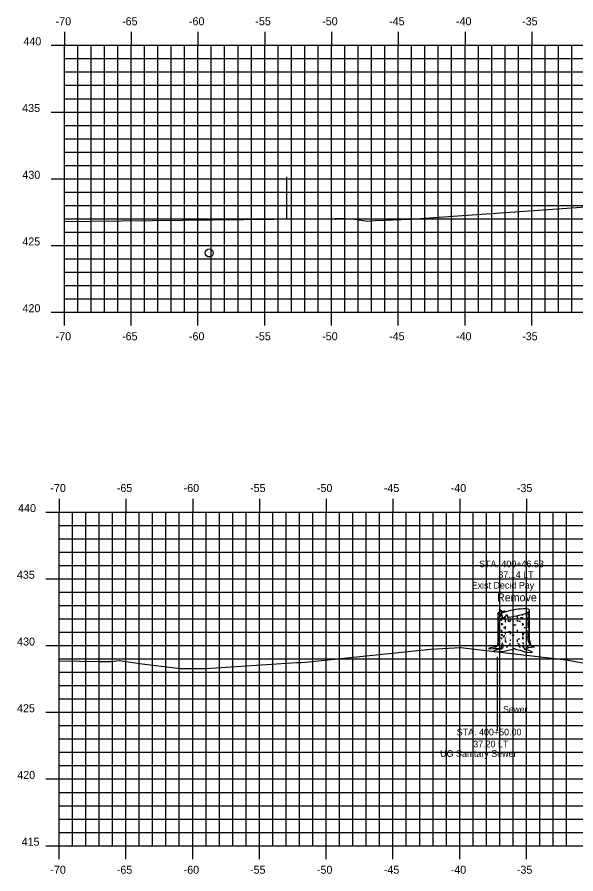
# Model space of a CAD drawing. Extents: x -161 to 764, y 111 to 210.
# Drawn here: x 81 to 122.9, y 125.1 to 189.3 of the extents above; entities that cross this region are included whole.
import ezdxf

# ---------------------------------------------------------------- set-up
doc = ezdxf.new("R2010")
doc.units = 0
for name, color, linetype in [('D_Text_Monospaced', 7, 'Continuous'), ('D_Text_Standard', 7, 'Continuous'), ('H_V ANNOTATION', 7, 'Continuous'), ('MAJOR', 7, 'Continuous'), ('MINOR', 7, 'Continuous'), ('S_Drainage_Culvert_Top', 7, 'Continuous'), ('S_Drainage_Invert', 7, 'Continuous'), ('S_Roadway_Centerline', 7, 'Continuous'), ('S_Trees_Decid_Pay', 7, 'Continuous'), ('S_Utilities_UG_Sanitary_Sewer', 7, 'Continuous')]:
    doc.layers.add(name, color=color, linetype=linetype)

msp = doc.modelspace()

# ---------------------------------------------------------------- linework, layer by layer
at = {"layer": 'MAJOR'}
for p, q in [((84.563, 188.143), (84.563, 187.141)), ((89.563, 188.143), (89.563, 187.141)), ((94.563, 188.143), (94.563, 187.141)), ((99.563, 188.143), (99.563, 187.141)), ((104.563, 188.143), (104.563, 187.141)), ((109.563, 188.143), (109.563, 187.141)), ((114.563, 188.143), (114.563, 187.141)), ((119.563, 188.143), (119.563, 187.141)), ((83.561, 187.141), (84.563, 187.141)), ((84.563, 187.141), (224.563, 187.141)), ((84.563, 167.141), (84.563, 187.141)), ((84.563, 167.141), (84.563, 187.141)), ((84.563, 187.141), (224.563, 187.141)), ((89.563, 167.141), (89.563, 187.141)), ((94.563, 167.141), (94.563, 187.141)), ((99.563, 167.141), (99.563, 187.141)), ((104.563, 167.141), (104.563, 187.141)), ((109.563, 167.141), (109.563, 187.141)), ((114.563, 167.141), (114.563, 187.141)), ((119.563, 167.141), (119.563, 187.141)), ((83.561, 182.141), (84.563, 182.141)), ((84.563, 182.141), (224.563, 182.141)), ((83.561, 177.141), (84.563, 177.141)), ((84.563, 177.141), (224.563, 177.141)), ((83.561, 172.141), (84.563, 172.141)), ((84.563, 172.141), (224.563, 172.141)), ((83.561, 167.141), (84.563, 167.141)), ((84.563, 167.141), (224.563, 167.141)), ((84.563, 167.141), (224.563, 167.141)), ((84.563, 166.139), (84.563, 167.141)), ((89.563, 166.139), (89.563, 167.141)), ((94.563, 166.139), (94.563, 167.141)), ((99.563, 166.139), (99.563, 167.141)), ((104.563, 166.139), (104.563, 167.141)), ((109.563, 166.139), (109.563, 167.141)), ((114.563, 166.139), (114.563, 167.141)), ((119.563, 166.139), (119.563, 167.141)), ((84.168, 153.171), (84.168, 152.169)), ((89.168, 153.171), (89.168, 152.169)), ((94.168, 153.171), (94.168, 152.169)), ((99.168, 153.171), (99.168, 152.169)), ((104.168, 153.171), (104.168, 152.169)), ((109.168, 153.171), (109.168, 152.169)), ((114.168, 153.171), (114.168, 152.169)), ((119.168, 153.171), (119.168, 152.169)), ((83.166, 152.169), (84.168, 152.169)), ((84.168, 152.169), (224.168, 152.169)), ((84.168, 127.169), (84.168, 152.169)), ((84.168, 127.169), (84.168, 152.169)), ((84.168, 152.169), (224.168, 152.169)), ((89.168, 127.169), (89.168, 152.169)), ((94.168, 127.169), (94.168, 152.169)), ((99.168, 127.169), (99.168, 152.169)), ((104.168, 127.169), (104.168, 152.169)), ((109.168, 127.169), (109.168, 152.169)), ((114.168, 127.169), (114.168, 152.169)), ((119.168, 127.169), (119.168, 152.169)), ((83.166, 147.169), (84.168, 147.169)), ((84.168, 147.169), (224.168, 147.169)), ((83.166, 142.169), (84.168, 142.169)), ((84.168, 142.169), (224.168, 142.169)), ((83.166, 137.169), (84.168, 137.169)), ((84.168, 137.169), (224.168, 137.169)), ((83.166, 132.169), (84.168, 132.169)), ((84.168, 132.169), (224.168, 132.169)), ((83.166, 127.169), (84.168, 127.169)), ((84.168, 127.169), (224.168, 127.169)), ((84.168, 127.169), (224.168, 127.169)), ((84.168, 126.167), (84.168, 127.169)), ((89.168, 126.167), (89.168, 127.169)), ((94.168, 126.167), (94.168, 127.169)), ((99.168, 126.167), (99.168, 127.169)), ((104.168, 126.167), (104.168, 127.169)), ((109.168, 126.167), (109.168, 127.169)), ((114.168, 126.167), (114.168, 127.169)), ((119.168, 126.167), (119.168, 127.169))]:
    msp.add_line(p, q, dxfattribs=at)
at = {"layer": 'MINOR'}
for p, q in [((85.563, 167.141), (85.563, 187.141)), ((86.563, 167.141), (86.563, 187.141)), ((87.563, 167.141), (87.563, 187.141)), ((88.563, 167.141), (88.563, 187.141)), ((90.563, 167.141), (90.563, 187.141)), ((91.563, 167.141), (91.563, 187.141)), ((92.563, 167.141), (92.563, 187.141)), ((93.563, 167.141), (93.563, 187.141)), ((95.563, 167.141), (95.563, 187.141)), ((96.563, 167.141), (96.563, 187.141)), ((97.563, 167.141), (97.563, 187.141)), ((98.563, 167.141), (98.563, 187.141)), ((100.563, 167.141), (100.563, 187.141)), ((101.563, 167.141), (101.563, 187.141)), ((102.563, 167.141), (102.563, 187.141)), ((103.563, 167.141), (103.563, 187.141)), ((105.563, 167.141), (105.563, 187.141)), ((106.563, 167.141), (106.563, 187.141)), ((107.563, 167.141), (107.563, 187.141)), ((108.563, 167.141), (108.563, 187.141)), ((110.563, 167.141), (110.563, 187.141)), ((111.563, 167.141), (111.563, 187.141)), ((112.563, 167.141), (112.563, 187.141)), ((113.563, 167.141), (113.563, 187.141)), ((115.563, 167.141), (115.563, 187.141)), ((116.563, 167.141), (116.563, 187.141)), ((117.563, 167.141), (117.563, 187.141)), ((118.563, 167.141), (118.563, 187.141)), ((120.563, 167.141), (120.563, 187.141)), ((121.563, 167.141), (121.563, 187.141)), ((122.563, 167.141), (122.563, 187.141)), ((84.563, 186.141), (224.563, 186.141)), ((84.563, 186.141), (85.565, 186.141)), ((84.563, 185.141), (224.563, 185.141)), ((84.563, 185.141), (85.565, 185.141)), ((84.563, 184.141), (224.563, 184.141)), ((84.563, 184.141), (85.565, 184.141)), ((84.563, 183.141), (224.563, 183.141)), ((84.563, 183.141), (85.565, 183.141)), ((84.563, 181.141), (224.563, 181.141)), ((84.563, 181.141), (85.565, 181.141)), ((84.563, 180.141), (224.563, 180.141)), ((84.563, 180.141), (85.565, 180.141)), ((84.563, 179.141), (224.563, 179.141)), ((84.563, 179.141), (85.565, 179.141)), ((84.563, 178.141), (224.563, 178.141)), ((84.563, 178.141), (85.565, 178.141)), ((84.563, 176.141), (224.563, 176.141)), ((84.563, 176.141), (85.565, 176.141)), ((84.563, 175.141), (224.563, 175.141)), ((84.563, 175.141), (85.565, 175.141)), ((84.563, 174.141), (224.563, 174.141)), ((84.563, 174.141), (85.565, 174.141)), ((84.563, 173.141), (224.563, 173.141)), ((84.563, 173.141), (85.565, 173.141)), ((84.563, 171.141), (224.563, 171.141)), ((84.563, 171.141), (85.565, 171.141)), ((84.563, 170.141), (224.563, 170.141)), ((84.563, 170.141), (85.565, 170.141)), ((84.563, 169.141), (224.563, 169.141)), ((84.563, 169.141), (85.565, 169.141)), ((84.563, 168.141), (224.563, 168.141)), ((84.563, 168.141), (85.565, 168.141)), ((85.168, 127.169), (85.168, 152.169)), ((86.168, 127.169), (86.168, 152.169)), ((87.168, 127.169), (87.168, 152.169)), ((88.168, 127.169), (88.168, 152.169)), ((90.168, 127.169), (90.168, 152.169)), ((91.168, 127.169), (91.168, 152.169)), ((92.168, 127.169), (92.168, 152.169)), ((93.168, 127.169), (93.168, 152.169)), ((95.168, 127.169), (95.168, 152.169)), ((96.168, 127.169), (96.168, 152.169)), ((97.168, 127.169), (97.168, 152.169)), ((98.168, 127.169), (98.168, 152.169)), ((100.168, 127.169), (100.168, 152.169)), ((101.168, 127.169), (101.168, 152.169)), ((102.168, 127.169), (102.168, 152.169)), ((103.168, 127.169), (103.168, 152.169)), ((105.168, 127.169), (105.168, 152.169)), ((106.168, 127.169), (106.168, 152.169)), ((107.168, 127.169), (107.168, 152.169)), ((108.168, 127.169), (108.168, 152.169)), ((110.168, 127.169), (110.168, 152.169)), ((111.168, 127.169), (111.168, 152.169)), ((112.168, 127.169), (112.168, 152.169)), ((113.168, 127.169), (113.168, 152.169)), ((115.168, 127.169), (115.168, 152.169)), ((116.168, 127.169), (116.168, 152.169)), ((117.168, 127.169), (117.168, 152.169)), ((118.168, 127.169), (118.168, 152.169)), ((120.168, 127.169), (120.168, 152.169)), ((121.168, 127.169), (121.168, 152.169)), ((122.168, 127.169), (122.168, 152.169)), ((84.168, 151.169), (224.168, 151.169)), ((84.168, 151.169), (85.17, 151.169)), ((84.168, 150.169), (224.168, 150.169)), ((84.168, 150.169), (85.17, 150.169)), ((84.168, 149.169), (224.168, 149.169)), ((84.168, 149.169), (85.17, 149.169)), ((84.168, 148.169), (224.168, 148.169)), ((84.168, 148.169), (85.17, 148.169)), ((84.168, 146.169), (224.168, 146.169)), ((84.168, 146.169), (85.17, 146.169)), ((84.168, 145.169), (224.168, 145.169)), ((84.168, 145.169), (85.17, 145.169)), ((84.168, 144.169), (224.168, 144.169)), ((84.168, 144.169), (85.17, 144.169)), ((84.168, 143.169), (224.168, 143.169)), ((84.168, 143.169), (85.17, 143.169)), ((84.168, 141.169), (224.168, 141.169)), ((84.168, 141.169), (85.17, 141.169)), ((84.168, 140.169), (224.168, 140.169)), ((84.168, 140.169), (85.17, 140.169)), ((84.168, 139.169), (224.168, 139.169)), ((84.168, 139.169), (85.17, 139.169)), ((84.168, 138.169), (224.168, 138.169)), ((84.168, 138.169), (85.17, 138.169)), ((84.168, 136.169), (224.168, 136.169)), ((84.168, 136.169), (85.17, 136.169)), ((84.168, 135.169), (224.168, 135.169)), ((84.168, 135.169), (85.17, 135.169)), ((84.168, 134.169), (224.168, 134.169)), ((84.168, 134.169), (85.17, 134.169)), ((84.168, 133.169), (224.168, 133.169)), ((84.168, 133.169), (85.17, 133.169)), ((84.168, 131.169), (224.168, 131.169)), ((84.168, 131.169), (85.17, 131.169)), ((84.168, 130.169), (224.168, 130.169)), ((84.168, 130.169), (85.17, 130.169)), ((84.168, 129.169), (224.168, 129.169)), ((84.168, 129.169), (85.17, 129.169)), ((84.168, 128.169), (224.168, 128.169)), ((84.168, 128.169), (85.17, 128.169))]:
    msp.add_line(p, q, dxfattribs=at)
at = {"layer": 'S_Drainage_Culvert_Top'}
msp.add_line((101.194, 177.288), (101.194, 174.133), dxfattribs=at)
at = {"layer": 'S_Drainage_Invert'}
msp.add_circle((95.412, 171.579), 0.3, dxfattribs=at)
at = {"layer": 'S_Roadway_Centerline'}
for points in [[(84.563, 173.937), (86.565, 173.962), (104.807, 174.158), (105.264, 174.178), (106.296, 174.117), (107.265, 173.972), (107.828, 174.003), (110.477, 174.125), (125.033, 175.141), (130.13, 175.365), (150.707, 176.49), (164.616, 177.272), (172.022, 177.096), (179.352, 177.108), (186.535, 177.007), (193.367, 177.096), (200.259, 176.65), (200.943, 176.413), (208.506, 176.123), (214.429, 175.907), (217.362, 175.08), (224.563, 174.564)], [(84.168, 141.029), (87.203, 140.965), (88.029, 140.976), (88.313, 140.998), (88.651, 141.037), (90.373, 140.805), (93.242, 140.453), (95.167, 140.458), (101.949, 140.906), (102.274, 140.898), (102.611, 140.922), (111.988, 141.903), (114.233, 142.01), (122.137, 141.107), (126.555, 140.289), (130.319, 140.459), (134.216, 140.564), (135.604, 140.561), (137.09, 140.487), (138.288, 140.324), (142.564, 140.487), (147.286, 140.317), (152.685, 140.854), (168.169, 142.293)]]:
    msp.add_lwpolyline(points, dxfattribs=at)
at = {"layer": 'S_Trees_Decid_Pay'}
for p, q in [((117.223, 144.514), (117.223, 144.34)), ((118.863, 144.506), (118.863, 144.42)), ((119.268, 144.673), (119.268, 144.42)), ((119.348, 144.718), (119.348, 144.597)), ((119.348, 144.545), (119.348, 144.331)), ((117.073, 144.314), (117.073, 144.06)), ((117.073, 143.962), (117.073, 143.493)), ((117.159, 144.168), (117.159, 143.957)), ((117.159, 143.891), (117.159, 143.743)), ((117.308, 144.266), (117.308, 144.061)), ((117.308, 143.854), (117.308, 143.699)), ((117.569, 144.268), (117.569, 144.148)), ((117.569, 144.096), (117.569, 143.911)), ((117.807, 143.996), (117.812, 144.103)), ((117.934, 144.168), (117.934, 143.989)), ((118.48, 144.405), (118.48, 144.125)), ((118.48, 144.06), (118.48, 143.957)), ((118.863, 144.279), (118.863, 144.14)), ((118.863, 143.854), (118.863, 143.662)), ((119.135, 144.42), (119.135, 144.228)), ((119.135, 143.977), (119.135, 143.699)), ((119.268, 144.323), (119.268, 144.06)), ((119.268, 143.962), (119.268, 143.654)), ((119.348, 144.286), (119.348, 143.948)), ((119.348, 143.831), (119.348, 143.47)), ((117.073, 143.442), (117.073, 143.308)), ((117.073, 143.25), (117.073, 142.925)), ((117.159, 143.565), (117.159, 143.265)), ((117.159, 143.228), (117.159, 142.985)), ((117.308, 143.336), (117.308, 143.117)), ((117.569, 143.625), (117.569, 143.397)), ((117.569, 143.199), (117.569, 143.014)), ((117.934, 143.21), (117.934, 143.014)), ((118.48, 143.345), (118.48, 143.125)), ((118.863, 143.182), (118.863, 142.974)), ((119.135, 143.654), (119.135, 143.545)), ((119.135, 143.411), (119.135, 143.182)), ((119.268, 143.565), (119.268, 143.499)), ((119.268, 143.265), (119.268, 143.168)), ((119.348, 143.434), (119.348, 142.985)), ((117.073, 142.896), (117.073, 142.476)), ((117.159, 142.874), (117.159, 142.733)), ((117.159, 142.602), (117.159, 142.445)), ((117.308, 143.017), (117.308, 142.896)), ((117.308, 142.745), (117.308, 142.647)), ((117.569, 142.779), (117.569, 142.702)), ((117.569, 142.625), (117.569, 142.451)), ((117.934, 142.63), (117.934, 142.527)), ((118.48, 142.625), (118.48, 142.451)), ((118.863, 142.853), (118.863, 142.653)), ((119.135, 142.853), (119.135, 142.47)), ((119.268, 143.117), (119.268, 142.756)), ((119.268, 142.705), (119.268, 142.538)), ((119.348, 142.919), (119.348, 142.637)), ((117.077, 142.373), (117.062, 142.256)), ((118.858, 142.396), (118.938, 142.264))]:
    msp.add_line(p, q, dxfattribs=at)
for points in [[(117.023, 144.588), (117.023, 142.451), (117.003, 142.31), (116.997, 142.184), (116.953, 142.097), (116.861, 142.048), (116.725, 142.048), (116.482, 141.992), (116.315, 141.943), (116.457, 141.912), (116.694, 141.949), (116.904, 141.937), (117.165, 141.943), (117.289, 141.961), (117.32, 141.918), (117.382, 141.961), (117.283, 141.894), (117.048, 141.869), (116.818, 141.807), (116.688, 141.737), (116.787, 141.693), (117.209, 141.712), (117.487, 141.756), (117.785, 141.832), (118.071, 141.869), (118.176, 141.869), (118.195, 141.949), (118.263, 141.955), (118.43, 141.869), (118.716, 141.813), (119.014, 141.706), (119.474, 141.657), (119.628, 141.669), (119.286, 141.819), (119.083, 141.85), (119.094, 141.924), (119.354, 142.023), (119.53, 142.054), (119.77, 142.066), (119.572, 142.104), (119.51, 142.14), (119.486, 142.227), (119.474, 142.396), (119.428, 142.482), (119.4, 142.723), (119.4, 144.809)], [(117.379, 144.261), (117.371, 144.405), (117.326, 144.397), (117.312, 144.772), (117.217, 144.78), (117.203, 144.86), (117.165, 144.523), (117.12, 144.617), (117.1, 144.463), (117.023, 144.588), (117.029, 144.399)], [(117.023, 144.588), (117.069, 144.611), (117.091, 144.677), (117.143, 144.7), (117.176, 144.625)], [(117.402, 144.627), (117.423, 144.735), (117.554, 144.766), (117.562, 144.678)], [(117.541, 144.266), (117.577, 144.369), (117.643, 144.375), (117.643, 144.457), (117.717, 144.463), (117.742, 144.283)], [(117.431, 142.896), (117.423, 142.822), (117.497, 142.816), (117.511, 142.933)], [(118.976, 142.988), (118.975, 143.065), (118.967, 143.131)], [(119.35, 142.565), (119.41, 142.404), (119.424, 142.279), (119.416, 142.182)], [(117.143, 142.381), (117.136, 142.256), (117.054, 142.161)], [(117.289, 141.961), (117.308, 142.14), (117.369, 142.277), (117.363, 142.377)], [(117.48, 142.209), (117.406, 142.14), (117.388, 142.042), (117.382, 141.961)], [(117.932, 142.344), (117.915, 142.19), (117.717, 142.109), (117.672, 142.006)], [(118.497, 142.336), (118.6, 142.285), (118.615, 142.079), (118.718, 142.05)], [(119.083, 141.85), (118.996, 141.992), (118.864, 142.134)], [(119.152, 142.41), (119.152, 142.205), (119.21, 142.095), (119.307, 142.079)], [(119.293, 142.484), (119.364, 142.381), (119.364, 142.256)]]:
    msp.add_lwpolyline(points, dxfattribs=at)
for centre, radius, start, end in [((117.833, 143.401), 1.299, 107.86134, 113.3069), ((119.313, 138.807), 6.126, 100.77788, 107.86134), ((119.313, 138.807), 6.126, 93.69441, 100.77788), ((117.111, 150.376), 6.126, 280.77788, 287.86134), ((119.002, 143.624), 1.299, 78.27788, 93.69441), ((118.591, 145.782), 1.299, 287.86134, 303.27788), ((119.168, 144.427), 0.48, 69.98432, 78.27788), ((119.041, 145.097), 0.48, 303.27788, 311.57144), ((119.276, 144.723), 0.164, 55.77788, 69.98432), ((119.261, 144.552), 0.166, 301.67004, 315), ((119.25, 144.861), 0.164, 311.57144, 325.77788), ((119.308, 144.77), 0.107, 45.9547, 55.77788), ((119.301, 144.511), 0.109, 315, 324.82628), ((119.338, 144.801), 0.0645, 33.27788, 45.9547), ((119.297, 144.829), 0.107, 325.77788, 335.60106), ((119.337, 144.486), 0.0657, 324.82628, 337.5), ((119.347, 144.806), 0.0544, 22.46002, 33.27788), ((119.336, 144.811), 0.0645, 335.60106, 348.27788), ((119.354, 144.809), 0.0467, 10.77788, 22.46002), ((119.346, 144.482), 0.0554, 337.5, 348.31854), ((119.346, 144.809), 0.0544, 348.27788, 359.09574), ((119.354, 144.809), 0.0467, 359.09574, 10.77788), ((117.071, 144.22), 0.0476, 180, 191.68146), ((117.079, 144.222), 0.0554, 191.68146, 202.5), ((117.088, 144.226), 0.0657, 202.5, 215.17372), ((117.123, 144.251), 0.109, 215.17372, 225), ((117.164, 144.291), 0.166, 225, 239.19244), ((117.164, 144.028), 0.166, 237.03779, 239.19244), ((117.327, 144.301), 0.484, 239.19244, 247.5), ((117.636, 145.047), 1.292, 247.5, 248.35373), ((117.636, 145.31), 1.292, 250.61187, 255.28558), ((117.636, 145.047), 1.292, 255.28558, 259.26323), ((117.422, 145.56), 1.299, 268.12894, 273.69441), ((117.111, 150.376), 6.126, 273.69441, 274.02462), ((117.111, 150.376), 6.126, 275.91473, 280.77788), ((118.212, 149.898), 5.916, 266.07764, 267.30434), ((118.212, 149.898), 5.916, 273.53821, 274.89239), ((118.213, 150.159), 5.916, 274.95145, 276.30875), ((118.789, 145.571), 1.292, 285.56512, 289.09156), ((118.788, 145.31), 1.292, 288.08294, 292.5), ((118.788, 145.047), 1.292, 291.8071, 292.5), ((119.097, 144.301), 0.484, 292.5, 300.80756), ((119.097, 144.564), 0.484, 297.41617, 300.80756), ((119.26, 144.291), 0.166, 300.80756, 315), ((119.26, 144.028), 0.166, 300.80756, 301.6001), ((119.3, 144.251), 0.109, 315, 324.82628), ((119.336, 144.226), 0.0657, 324.82628, 337.5), ((119.345, 144.222), 0.0554, 337.5, 348.31854), ((117.071, 143.699), 0.0476, 180, 191.68146), ((117.071, 143.442), 0.0476, 180, 191.68146), ((117.071, 143.176), 0.0476, 180, 191.68146), ((117.079, 143.701), 0.0554, 191.68146, 202.5), ((117.079, 143.443), 0.0554, 191.68146, 202.5), ((117.079, 143.178), 0.0554, 191.68146, 202.5), ((117.088, 143.705), 0.0657, 202.5, 215.17372), ((117.088, 143.447), 0.0657, 202.5, 215.17372), ((117.088, 143.182), 0.0657, 202.5, 215.17372), ((117.123, 143.73), 0.109, 215.17372, 225), ((117.123, 143.472), 0.109, 215.17372, 225), ((117.123, 143.207), 0.109, 215.17372, 225), ((117.164, 143.77), 0.166, 225, 239.19244), ((117.164, 143.513), 0.166, 225, 239.19244), ((117.327, 144.043), 0.484, 239.19244, 245.77245), ((117.636, 144.789), 1.292, 247.5, 248.48417), ((117.636, 144.532), 1.292, 247.5, 251.79898), ((117.636, 144.789), 1.292, 261.87257, 262.84537), ((118.212, 149.377), 5.916, 262.84537, 263.7595), ((118.212, 149.12), 5.916, 266.27211, 267.30434), ((118.212, 149.635), 5.916, 270.1162, 271.77083), ((118.212, 149.635), 5.916, 276.31835, 277.15462), ((118.788, 145.047), 1.292, 277.15462, 278.36619), ((118.788, 144.789), 1.292, 279.25654, 285.6105), ((118.788, 144.532), 1.292, 285.61049, 290.10015), ((119.097, 144.043), 0.484, 294.63721, 300.80756), ((119.26, 143.77), 0.166, 300.80756, 315), ((119.26, 143.513), 0.166, 302.06939, 315), ((119.3, 143.73), 0.109, 315, 324.82628), ((119.3, 143.472), 0.109, 315, 324.82628), ((119.336, 143.705), 0.0657, 324.82628, 337.5), ((119.336, 143.447), 0.0657, 324.82628, 337.5), ((119.345, 143.701), 0.0554, 337.5, 348.31854), ((119.345, 143.443), 0.0554, 337.5, 348.31854), ((119.345, 143.178), 0.0554, 337.5, 348.31854), ((117.071, 142.647), 0.0476, 180, 191.68146), ((117.079, 142.649), 0.0554, 191.68146, 202.5), ((117.088, 142.653), 0.0657, 202.5, 215.17372), ((117.123, 142.678), 0.109, 215.17372, 225), ((117.164, 143.247), 0.166, 225, 239.19244), ((117.164, 142.718), 0.166, 225, 239.19244), ((117.327, 143.52), 0.484, 239.19244, 247.5), ((117.327, 142.991), 0.484, 239.19244, 247.5), ((117.327, 143.248), 0.484, 242.73401, 247.5), ((117.636, 144.267), 1.292, 247.5, 248.35373), ((117.636, 143.737), 1.292, 247.5, 248.35373), ((117.636, 143.995), 1.292, 251.36642, 255.28558), ((117.636, 144.267), 1.292, 255.28558, 259.24628), ((118.212, 148.854), 5.916, 268.92065, 270), ((118.212, 148.854), 5.916, 270, 270.27568), ((118.212, 148.583), 5.916, 273.26366, 274.46102), ((118.212, 148.854), 5.916, 276.31835, 277.15462), ((118.212, 148.583), 5.916, 276.31835, 277.15462), ((118.788, 144.267), 1.292, 277.15462, 278.37952), ((118.788, 143.995), 1.292, 277.15462, 278.36619), ((118.788, 143.995), 1.292, 285.61049, 289.15336), ((118.797, 143.741), 1.292, 291.36963, 292.0604), ((119.097, 143.52), 0.484, 292.5, 300.80756), ((119.097, 142.991), 0.484, 292.5, 296.54992), ((119.26, 143.247), 0.166, 300.80756, 302.06939), ((119.26, 142.975), 0.166, 302.06939, 315), ((119.3, 142.935), 0.109, 315, 324.82628), ((119.336, 142.91), 0.0657, 324.82628, 337.5), ((119.345, 142.906), 0.0554, 337.5, 348.31854), ((118.212, 148.325), 5.916, 263.78314, 264.76555)]:
    msp.add_arc(centre, radius, start, end, dxfattribs=at)
at = {"layer": 'S_Utilities_UG_Sanitary_Sewer'}
msp.add_line((116.963, 141.322), (116.963, 135.786), dxfattribs=at)

# ---------------------------------------------------------------- texts
at = {"layer": 'D_Text_Monospaced'}
for s, height, p in [('STA. 400+46.53', 0.49998, (115.616, 148.032)), ('37.14 LT', 0.5, (117.06, 147.225)), ('Exist Decid Pay', 0.49998, (115.064, 146.436)), ('STA. 400+50.00', 0.49998, (113.94, 135.433)), ('37.20 LT', 0.5, (115.177, 134.542)), ('UG Sanitary Sewer', 0.49998, (112.699, 133.827))]:
    msp.add_text(s, height=height, dxfattribs=at).set_placement(p)
at = {"layer": 'D_Text_Standard'}
msp.add_text('Remove', height=0.6, dxfattribs=at).set_placement((116.957, 145.477))
at = {"layer": 'H_V ANNOTATION'}
for s, p in [('-70', (83.905, 188.641)), ('-65', (88.881, 188.641)), ('-60', (93.889, 188.641)), ('-55', (98.859, 188.641)), ('-50', (103.867, 188.641)), ('-45', (108.881, 188.641)), ('-40', (113.889, 188.641)), ('-35', (118.843, 188.641)), ('440', (81.49, 187.141)), ('435', (81.399, 182.141)), ('430', (81.415, 177.141)), ('425', (81.409, 172.141)), ('420', (81.425, 167.141)), ('-70', (83.905, 165.041)), ('-65', (88.881, 165.041)), ('-60', (93.889, 165.041)), ('-55', (98.859, 165.041)), ('-50', (103.867, 165.041)), ('-45', (108.881, 165.041)), ('-40', (113.889, 165.041)), ('-35', (118.843, 165.041)), ('-70', (83.509, 153.669)), ('-65', (88.485, 153.669)), ('-60', (93.493, 153.669)), ('-55', (98.464, 153.669)), ('-50', (103.472, 153.669)), ('-45', (108.485, 153.669)), ('-40', (113.493, 153.669)), ('-35', (118.448, 153.669)), ('440', (81.094, 152.169)), ('435', (81.003, 147.169)), ('430', (81.019, 142.169)), ('425', (81.014, 137.169)), ('420', (81.03, 132.169)), ('415', (81.356, 127.169)), ('-70', (83.509, 125.069)), ('-65', (88.485, 125.069)), ('-60', (93.493, 125.069)), ('-55', (98.464, 125.069)), ('-50', (103.472, 125.069)), ('-45', (108.485, 125.069)), ('-40', (113.493, 125.069)), ('-35', (118.448, 125.069))]:
    msp.add_text(s, height=0.6, rotation=360, dxfattribs=at).set_placement(p)
at = {"layer": 'MAJOR'}
for p in [(84.559, 167.141), (84.163, 127.169)]:
    msp.add_text('-', height=1.5248952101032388e-17, rotation=53.1301, dxfattribs=at).set_placement(p)
at = {"layer": 'S_Utilities_UG_Sanitary_Sewer'}
msp.add_text('Sewer', height=0.4798, rotation=360, dxfattribs=at).set_placement((117.414, 137.152))

doc.saveas('drawing.dxf')
